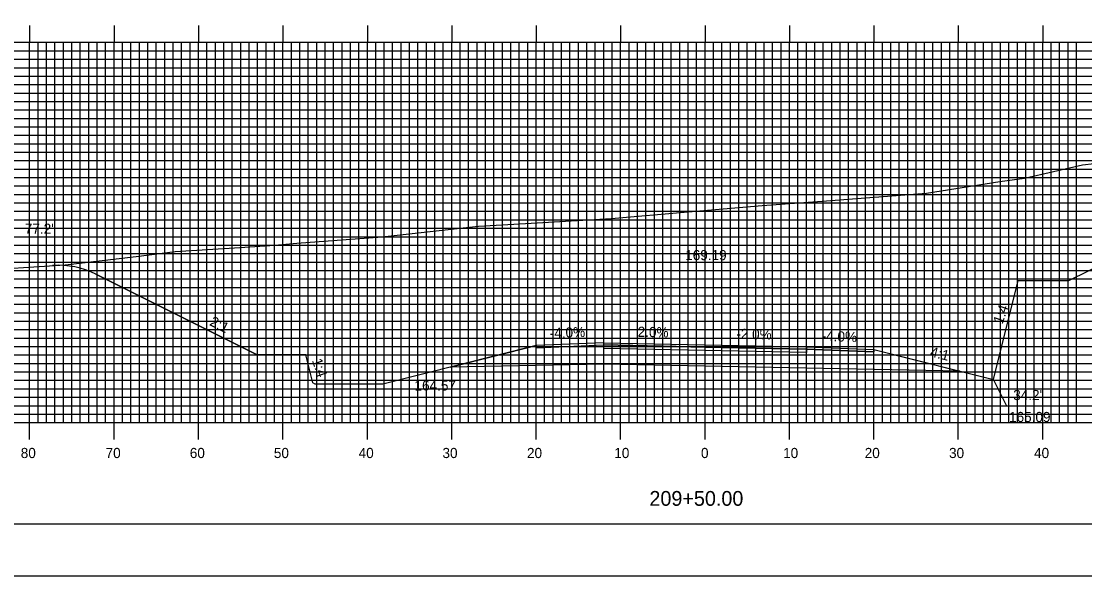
# Model space of a CAD drawing. Extents: x 1794453 to 1794796, y 442591 to 442811.
# Drawn here: x 1794537.4 to 1794663.3, y 442590.5 to 442656.2 of the extents above; entities that cross this region are included whole.
import ezdxf

# ---------------------------------------------------------------- set-up
doc = ezdxf.new("R2010")
doc.units = 0
for name, color, linetype in [('ANNOTATION', 7, 'Continuous'), ('BORDER', 7, 'Continuous'), ('D_Roadway_Centerline', 7, 'Continuous'), ('D_Roadway_Centerline_Text', 7, 'Continuous'), ('D_Roadway_Edge_Shoulder', 7, 'Continuous'), ('D_Roadway_Edge_TW', 7, 'Continuous'), ('D_Roadway_FinishedGrade', 7, 'Continuous'), ('D_Roadway_Pavement', 7, 'Continuous'), ('D_Roadway_SlopeLines', 7, 'Continuous'), ('D_Roadway_SubGrade', 7, 'Continuous'), ('D_Text_Standard', 7, 'Continuous'), ('H_V ANNOTATION', 7, 'Continuous'), ('MAJOR', 7, 'Continuous'), ('MINOR', 7, 'Continuous'), ('PLOT BOUNDARY', 7, 'Continuous'), ('S_Roadway_Centerline', 7, 'Continuous')]:
    doc.layers.add(name, color=color, linetype=linetype)

msp = doc.modelspace()

# ---------------------------------------------------------------- linework, layer by layer
at = {"layer": 'ANNOTATION'}
msp.add_lwpolyline([(1794659.79, 442610.6), (1794654.1, 442610.6), (1794652.51, 442613.75)], dxfattribs=at)
at = {"layer": 'BORDER'}
msp.add_lwpolyline([(1794468.74, 442596.67), (1794788.74, 442596.67), (1794788.74, 442806.67), (1794468.74, 442806.67)], close=True, dxfattribs=at)
at = {"layer": 'D_Roadway_Centerline'}
msp.add_lwpolyline([(1794546.19, 442626.22), (1794565.3, 442616.67)], dxfattribs=at)
at = {"layer": 'D_Roadway_Edge_Shoulder'}
for points in [[(1794606.34, 442618.1), (1794598.34, 442617.78), (1794598.34, 442617.53), (1794606.34, 442617.85)], [(1794630.34, 442617.62), (1794638.34, 442617.3), (1794638.34, 442617.05), (1794630.34, 442617.37)]]:
    msp.add_lwpolyline(points, close=True, dxfattribs=at)
at = {"layer": 'D_Roadway_Edge_TW'}
msp.add_lwpolyline([(1794606.34, 442617.85), (1794606.34, 442618.1), (1794618.34, 442617.86), (1794630.34, 442617.62), (1794630.34, 442617.37), (1794618.34, 442617.61)], close=True, dxfattribs=at)
at = {"layer": 'D_Roadway_FinishedGrade'}
for points in [[(1794565.3, 442616.67), (1794546.19, 442626.22)], [(1794580.17, 442613.23), (1794572.17, 442613.23), (1794571.88, 442613.37)]]:
    msp.add_lwpolyline(points, dxfattribs=at)
msp.add_arc((1794541.72, 442617.28), 10, 63.4349, 93.7377, dxfattribs=at)
at = {"layer": 'D_Roadway_Pavement'}
msp.add_lwpolyline([(1794606.34, 442617.43), (1794606.34, 442617.85), (1794618.34, 442617.61), (1794630.34, 442617.37), (1794630.34, 442616.95), (1794618.34, 442617.19)], close=True, dxfattribs=at)
at = {"layer": 'D_Roadway_SlopeLines'}
for p, q in [((1794661.44, 442625.47), (1794685.8, 442637.64)), ((1794652.51, 442613.75), (1794655.44, 442625.47)), ((1794655.44, 442625.47), (1794661.44, 442625.47))]:
    msp.add_line(p, q, dxfattribs=at)
for points in [[(1794598.34, 442617.78), (1794580.17, 442613.23)], [(1794571.88, 442613.37), (1794571.06, 442616.67), (1794565.3, 442616.67)], [(1794638.34, 442617.3), (1794652.51, 442613.75)]]:
    msp.add_lwpolyline(points, dxfattribs=at)
at = {"layer": 'D_Roadway_SubGrade'}
msp.add_lwpolyline([(1794606.34, 442615.6), (1794588.17, 442615.23), (1794598.34, 442617.78), (1794598.34, 442617.53), (1794606.34, 442617.85), (1794618.34, 442617.61), (1794630.34, 442617.37), (1794638.34, 442617.05), (1794638.34, 442617.3), (1794648.51, 442614.75), (1794630.34, 442615.12), (1794618.34, 442615.36)], close=True, dxfattribs=at)
at = {"layer": 'MAJOR'}
for p, q in [((1794538.34, 442655.67), (1794538.34, 442653.67)), ((1794548.34, 442655.67), (1794548.34, 442653.67)), ((1794558.34, 442655.67), (1794558.34, 442653.67)), ((1794568.34, 442655.67), (1794568.34, 442653.67)), ((1794578.34, 442655.67), (1794578.34, 442653.67)), ((1794588.34, 442655.67), (1794588.34, 442653.67)), ((1794598.34, 442655.67), (1794598.34, 442653.67)), ((1794608.34, 442655.67), (1794608.34, 442653.67)), ((1794618.34, 442655.67), (1794618.34, 442653.67)), ((1794628.34, 442655.67), (1794628.34, 442653.67)), ((1794638.34, 442655.67), (1794638.34, 442653.67)), ((1794648.34, 442655.67), (1794648.34, 442653.67)), ((1794658.34, 442655.67), (1794658.34, 442653.67)), ((1794478.34, 442653.67), (1794758.34, 442653.67)), ((1794478.34, 442653.67), (1794758.34, 442653.67)), ((1794538.34, 442608.67), (1794538.34, 442653.67)), ((1794548.34, 442608.67), (1794548.34, 442653.67)), ((1794558.34, 442608.67), (1794558.34, 442653.67)), ((1794568.34, 442608.67), (1794568.34, 442653.67)), ((1794578.34, 442608.67), (1794578.34, 442653.67)), ((1794588.34, 442608.67), (1794588.34, 442653.67)), ((1794598.34, 442608.67), (1794598.34, 442653.67)), ((1794608.34, 442608.67), (1794608.34, 442653.67)), ((1794618.34, 442608.67), (1794618.34, 442653.67)), ((1794628.34, 442608.67), (1794628.34, 442653.67)), ((1794638.34, 442608.67), (1794638.34, 442653.67)), ((1794648.34, 442608.67), (1794648.34, 442653.67)), ((1794658.34, 442608.67), (1794658.34, 442653.67)), ((1794478.34, 442648.67), (1794758.34, 442648.67)), ((1794478.34, 442643.67), (1794758.34, 442643.67)), ((1794478.34, 442638.67), (1794758.34, 442638.67)), ((1794478.34, 442633.67), (1794758.34, 442633.67)), ((1794478.34, 442628.67), (1794758.34, 442628.67)), ((1794478.34, 442623.67), (1794758.34, 442623.67)), ((1794478.34, 442618.67), (1794758.34, 442618.67)), ((1794478.34, 442613.67), (1794758.34, 442613.67)), ((1794478.34, 442608.67), (1794758.34, 442608.67)), ((1794478.34, 442608.67), (1794758.34, 442608.67)), ((1794538.34, 442606.66), (1794538.34, 442608.67)), ((1794548.34, 442606.66), (1794548.34, 442608.67)), ((1794558.34, 442606.66), (1794558.34, 442608.67)), ((1794568.34, 442606.66), (1794568.34, 442608.67)), ((1794578.34, 442606.66), (1794578.34, 442608.67)), ((1794588.34, 442606.66), (1794588.34, 442608.67)), ((1794598.34, 442606.66), (1794598.34, 442608.67)), ((1794608.34, 442606.66), (1794608.34, 442608.67)), ((1794618.34, 442606.66), (1794618.34, 442608.67)), ((1794628.34, 442606.66), (1794628.34, 442608.67)), ((1794638.34, 442606.66), (1794638.34, 442608.67)), ((1794648.34, 442606.66), (1794648.34, 442608.67)), ((1794658.34, 442606.66), (1794658.34, 442608.67))]:
    msp.add_line(p, q, dxfattribs=at)
at = {"layer": 'MINOR'}
for p, q in [((1794478.34, 442652.67), (1794758.34, 442652.67)), ((1794539.34, 442608.67), (1794539.34, 442653.67)), ((1794540.34, 442608.67), (1794540.34, 442653.67)), ((1794541.34, 442608.67), (1794541.34, 442653.67)), ((1794542.34, 442608.67), (1794542.34, 442653.67)), ((1794543.34, 442608.67), (1794543.34, 442653.67)), ((1794544.34, 442608.67), (1794544.34, 442653.67)), ((1794545.34, 442608.67), (1794545.34, 442653.67)), ((1794546.34, 442608.67), (1794546.34, 442653.67)), ((1794547.34, 442608.67), (1794547.34, 442653.67)), ((1794549.34, 442608.67), (1794549.34, 442653.67)), ((1794550.34, 442608.67), (1794550.34, 442653.67)), ((1794551.34, 442608.67), (1794551.34, 442653.67)), ((1794552.34, 442608.67), (1794552.34, 442653.67)), ((1794553.34, 442608.67), (1794553.34, 442653.67)), ((1794554.34, 442608.67), (1794554.34, 442653.67)), ((1794555.34, 442608.67), (1794555.34, 442653.67)), ((1794556.34, 442608.67), (1794556.34, 442653.67)), ((1794557.34, 442608.67), (1794557.34, 442653.67)), ((1794559.34, 442608.67), (1794559.34, 442653.67)), ((1794560.34, 442608.67), (1794560.34, 442653.67)), ((1794561.34, 442608.67), (1794561.34, 442653.67)), ((1794562.34, 442608.67), (1794562.34, 442653.67)), ((1794563.34, 442608.67), (1794563.34, 442653.67)), ((1794564.34, 442608.67), (1794564.34, 442653.67)), ((1794565.34, 442608.67), (1794565.34, 442653.67)), ((1794566.34, 442608.67), (1794566.34, 442653.67)), ((1794567.34, 442608.67), (1794567.34, 442653.67)), ((1794569.34, 442608.67), (1794569.34, 442653.67)), ((1794570.34, 442608.67), (1794570.34, 442653.67)), ((1794571.34, 442608.67), (1794571.34, 442653.67)), ((1794572.34, 442608.67), (1794572.34, 442653.67)), ((1794573.34, 442608.67), (1794573.34, 442653.67)), ((1794574.34, 442608.67), (1794574.34, 442653.67)), ((1794575.34, 442608.67), (1794575.34, 442653.67)), ((1794576.34, 442608.67), (1794576.34, 442653.67)), ((1794577.34, 442608.67), (1794577.34, 442653.67)), ((1794579.34, 442608.67), (1794579.34, 442653.67)), ((1794580.34, 442608.67), (1794580.34, 442653.67)), ((1794581.34, 442608.67), (1794581.34, 442653.67)), ((1794582.34, 442608.67), (1794582.34, 442653.67)), ((1794583.34, 442608.67), (1794583.34, 442653.67)), ((1794584.34, 442608.67), (1794584.34, 442653.67)), ((1794585.34, 442608.67), (1794585.34, 442653.67)), ((1794586.34, 442608.67), (1794586.34, 442653.67)), ((1794587.34, 442608.67), (1794587.34, 442653.67)), ((1794589.34, 442608.67), (1794589.34, 442653.67)), ((1794590.34, 442608.67), (1794590.34, 442653.67)), ((1794591.34, 442608.67), (1794591.34, 442653.67)), ((1794592.34, 442608.67), (1794592.34, 442653.67)), ((1794593.34, 442608.67), (1794593.34, 442653.67)), ((1794594.34, 442608.67), (1794594.34, 442653.67)), ((1794595.34, 442608.67), (1794595.34, 442653.67)), ((1794596.34, 442608.67), (1794596.34, 442653.67)), ((1794597.34, 442608.67), (1794597.34, 442653.67)), ((1794599.34, 442608.67), (1794599.34, 442653.67)), ((1794600.34, 442608.67), (1794600.34, 442653.67)), ((1794601.34, 442608.67), (1794601.34, 442653.67)), ((1794602.34, 442608.67), (1794602.34, 442653.67)), ((1794603.34, 442608.67), (1794603.34, 442653.67)), ((1794604.34, 442608.67), (1794604.34, 442653.67)), ((1794605.34, 442608.67), (1794605.34, 442653.67)), ((1794606.34, 442608.67), (1794606.34, 442653.67)), ((1794607.34, 442608.67), (1794607.34, 442653.67)), ((1794609.34, 442608.67), (1794609.34, 442653.67)), ((1794610.34, 442608.67), (1794610.34, 442653.67)), ((1794611.34, 442608.67), (1794611.34, 442653.67)), ((1794612.34, 442608.67), (1794612.34, 442653.67)), ((1794613.34, 442608.67), (1794613.34, 442653.67)), ((1794614.34, 442608.67), (1794614.34, 442653.67)), ((1794615.34, 442608.67), (1794615.34, 442653.67)), ((1794616.34, 442608.67), (1794616.34, 442653.67)), ((1794617.34, 442608.67), (1794617.34, 442653.67)), ((1794619.34, 442608.67), (1794619.34, 442653.67)), ((1794620.34, 442608.67), (1794620.34, 442653.67)), ((1794621.34, 442608.67), (1794621.34, 442653.67)), ((1794622.34, 442608.67), (1794622.34, 442653.67)), ((1794623.34, 442608.67), (1794623.34, 442653.67)), ((1794624.34, 442608.67), (1794624.34, 442653.67)), ((1794625.34, 442608.67), (1794625.34, 442653.67)), ((1794626.34, 442608.67), (1794626.34, 442653.67)), ((1794627.34, 442608.67), (1794627.34, 442653.67)), ((1794629.34, 442608.67), (1794629.34, 442653.67)), ((1794630.34, 442608.67), (1794630.34, 442653.67)), ((1794631.34, 442608.67), (1794631.34, 442653.67)), ((1794632.34, 442608.67), (1794632.34, 442653.67)), ((1794633.34, 442608.67), (1794633.34, 442653.67)), ((1794634.34, 442608.67), (1794634.34, 442653.67)), ((1794635.34, 442608.67), (1794635.34, 442653.67)), ((1794636.34, 442608.67), (1794636.34, 442653.67)), ((1794637.34, 442608.67), (1794637.34, 442653.67)), ((1794639.34, 442608.67), (1794639.34, 442653.67)), ((1794640.34, 442608.67), (1794640.34, 442653.67)), ((1794641.34, 442608.67), (1794641.34, 442653.67)), ((1794642.34, 442608.67), (1794642.34, 442653.67)), ((1794643.34, 442608.67), (1794643.34, 442653.67)), ((1794644.34, 442608.67), (1794644.34, 442653.67)), ((1794645.34, 442608.67), (1794645.34, 442653.67)), ((1794646.34, 442608.67), (1794646.34, 442653.67)), ((1794647.34, 442608.67), (1794647.34, 442653.67)), ((1794649.34, 442608.67), (1794649.34, 442653.67)), ((1794650.34, 442608.67), (1794650.34, 442653.67)), ((1794651.34, 442608.67), (1794651.34, 442653.67)), ((1794652.34, 442608.67), (1794652.34, 442653.67)), ((1794653.34, 442608.67), (1794653.34, 442653.67)), ((1794654.34, 442608.67), (1794654.34, 442653.67)), ((1794655.34, 442608.67), (1794655.34, 442653.67)), ((1794656.34, 442608.67), (1794656.34, 442653.67)), ((1794657.34, 442608.67), (1794657.34, 442653.67)), ((1794659.34, 442608.67), (1794659.34, 442653.67)), ((1794660.34, 442608.67), (1794660.34, 442653.67)), ((1794661.34, 442608.67), (1794661.34, 442653.67)), ((1794662.34, 442608.67), (1794662.34, 442653.67)), ((1794478.34, 442651.67), (1794758.34, 442651.67)), ((1794478.34, 442650.67), (1794758.34, 442650.67)), ((1794478.34, 442649.67), (1794758.34, 442649.67)), ((1794478.34, 442647.67), (1794758.34, 442647.67)), ((1794478.34, 442646.67), (1794758.34, 442646.67)), ((1794478.34, 442645.67), (1794758.34, 442645.67)), ((1794478.34, 442644.67), (1794758.34, 442644.67)), ((1794478.34, 442642.67), (1794758.34, 442642.67)), ((1794478.34, 442641.67), (1794758.34, 442641.67)), ((1794478.34, 442640.67), (1794758.34, 442640.67)), ((1794478.34, 442639.67), (1794758.34, 442639.67)), ((1794478.34, 442637.67), (1794758.34, 442637.67)), ((1794478.34, 442636.67), (1794758.34, 442636.67)), ((1794478.34, 442635.67), (1794758.34, 442635.67)), ((1794478.34, 442634.67), (1794758.34, 442634.67)), ((1794478.34, 442632.67), (1794758.34, 442632.67)), ((1794478.34, 442631.67), (1794758.34, 442631.67)), ((1794478.34, 442630.67), (1794758.34, 442630.67)), ((1794478.34, 442629.67), (1794758.34, 442629.67)), ((1794478.34, 442627.67), (1794758.34, 442627.67)), ((1794478.34, 442626.67), (1794758.34, 442626.67)), ((1794478.34, 442625.67), (1794758.34, 442625.67)), ((1794478.34, 442624.67), (1794758.34, 442624.67)), ((1794478.34, 442622.67), (1794758.34, 442622.67)), ((1794478.34, 442621.67), (1794758.34, 442621.67)), ((1794478.34, 442620.67), (1794758.34, 442620.67)), ((1794478.34, 442619.67), (1794758.34, 442619.67)), ((1794478.34, 442617.67), (1794758.34, 442617.67)), ((1794478.34, 442616.67), (1794758.34, 442616.67)), ((1794478.34, 442615.67), (1794758.34, 442615.67)), ((1794478.34, 442614.67), (1794758.34, 442614.67)), ((1794478.34, 442612.67), (1794758.34, 442612.67)), ((1794478.34, 442611.67), (1794758.34, 442611.67)), ((1794478.34, 442610.67), (1794758.34, 442610.67)), ((1794478.34, 442609.67), (1794758.34, 442609.67))]:
    msp.add_line(p, q, dxfattribs=at)
at = {"layer": 'PLOT BOUNDARY'}
msp.add_lwpolyline([(1794452.55, 442590.55), (1794792.55, 442590.55), (1794792.55, 442810.55), (1794452.55, 442810.55)], close=True, dxfattribs=at)
at = {"layer": 'S_Roadway_Centerline'}
msp.add_lwpolyline([(1794531.41, 442626.62), (1794542.56, 442627.35), (1794550.97, 442628.32), (1794555.58, 442628.9), (1794563.25, 442629.4), (1794567.37, 442629.68), (1794569.98, 442629.92), (1794580.1, 442630.64), (1794588.26, 442631.54), (1794591.51, 442631.92), (1794598.44, 442632.31), (1794607.22, 442632.82), (1794616.34, 442633.59), (1794625.09, 442634.34), (1794632.2, 442634.88), (1794644.59, 442635.82), (1794653.27, 442637.2), (1794656.16, 442637.61), (1794663.05, 442639.17), (1794664.44, 442639.31)], dxfattribs=at)

# ---------------------------------------------------------------- texts
at = {"layer": 'ANNOTATION'}
for s, rotation, p in [('1:4', 70.516, (1794653.56, 442620.25)), ('1:4', 70.516, (1794653.56, 442620.25)), ('2:1', 333.4349, (1794559.57, 442620.23)), ('-4.0%', 2.2906, (1794599.97, 442618.64)), ('2.0%', 358.8542, (1794610.35, 442618.82)), ('-2.0%', 358.8542, (1794622.03, 442618.58)), ('-4.0%', 357.7094, (1794632.13, 442618.35)), ('4:1', 345.9638, (1794644.93, 442616.51)), ('1:4', 289.484, (1794571.76, 442616.02)), ('1:4', 289.484, (1794571.76, 442616.02))]:
    msp.add_text(s, height=1.2, rotation=rotation, dxfattribs=at).set_placement(p)
for s, p in [("34.2'", (1794654.84, 442611.33)), ('165.09', (1794654.35, 442608.73))]:
    msp.add_text(s, height=1.2, dxfattribs=at).set_placement(p)
at = {"layer": 'D_Roadway_Centerline'}
for s, p in [('C', (1794618.33, 442617.86)), ('L', (1794618.34, 442617.85))]:
    msp.add_text(s, height=0.0146, dxfattribs=at).set_placement(p)
at = {"layer": 'D_Roadway_Centerline_Text'}
msp.add_text('169.19', height=1.2, dxfattribs=at).set_placement((1794615.99, 442627.89))
at = {"layer": 'D_Text_Standard'}
for s, p in [("77.2'", (1794537.77, 442631.01)), ('164.57', (1794583.93, 442612.46))]:
    msp.add_text(s, height=1.2, dxfattribs=at).set_placement(p)
at = {"layer": 'H_V ANNOTATION'}
for s, height, p in [('80', 1.2, (1794537.29, 442604.47)), ('70', 1.2, (1794547.34, 442604.47)), ('60', 1.2, (1794557.31, 442604.47)), ('50', 1.2, (1794567.27, 442604.47)), ('40', 1.2, (1794577.31, 442604.47)), ('30', 1.2, (1794587.24, 442604.47)), ('20', 1.2, (1794597.25, 442604.47)), ('10', 1.2, (1794607.59, 442604.47)), ('0', 1.2, (1794617.86, 442604.47)), ('10', 1.2, (1794627.59, 442604.47)), ('20', 1.2, (1794637.25, 442604.47)), ('30', 1.2, (1794647.24, 442604.47)), ('40', 1.2, (1794657.31, 442604.47)), ('209+50.00', 1.75, (1794611.75, 442598.82))]:
    msp.add_text(s, height=height, dxfattribs=at).set_placement(p)

doc.saveas('drawing.dxf')
